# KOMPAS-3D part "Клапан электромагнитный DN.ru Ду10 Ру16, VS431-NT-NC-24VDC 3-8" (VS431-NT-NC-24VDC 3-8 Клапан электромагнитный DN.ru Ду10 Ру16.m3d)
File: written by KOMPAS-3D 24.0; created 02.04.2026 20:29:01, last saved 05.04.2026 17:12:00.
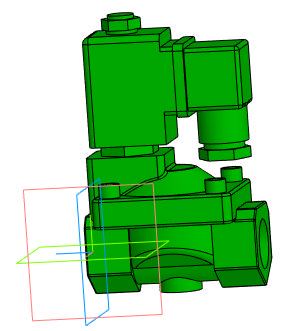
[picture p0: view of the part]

Document properties: Автор: artio; Полное имя файла: C:\Users\artio\OneDrive\Рабочий стол\Клапан электромагнитный DN.ru\VS431\VS431-NT-NC\VS431-NT-NC-24VDC\Ду10\VS431-NT-NC-24VDC 3-8 Клапан электромагнитный DN.ru Ду10 Ру16.m3d

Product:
- Body: Тело 1  | qty 1
    Масса: 1.030062
- Part/product: Клапан электромагнитный DN.ru Ду10 Ру16  | designation VS431-NT-NC-24VDC 3-8
    Масса: 0.62
    Раздел спецификации: Прочие изделия
    Примечание: D130-04746
    additional columns: ef56311e-7521-43dc-8291-0e6108b3d81d; VS400-ET-NC-220VAC 3-8; artio; c; Шероховатость не задана; Да

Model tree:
1. Операция без истории:1

Expressions: VS431-NT-NC-24VDC 3-8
